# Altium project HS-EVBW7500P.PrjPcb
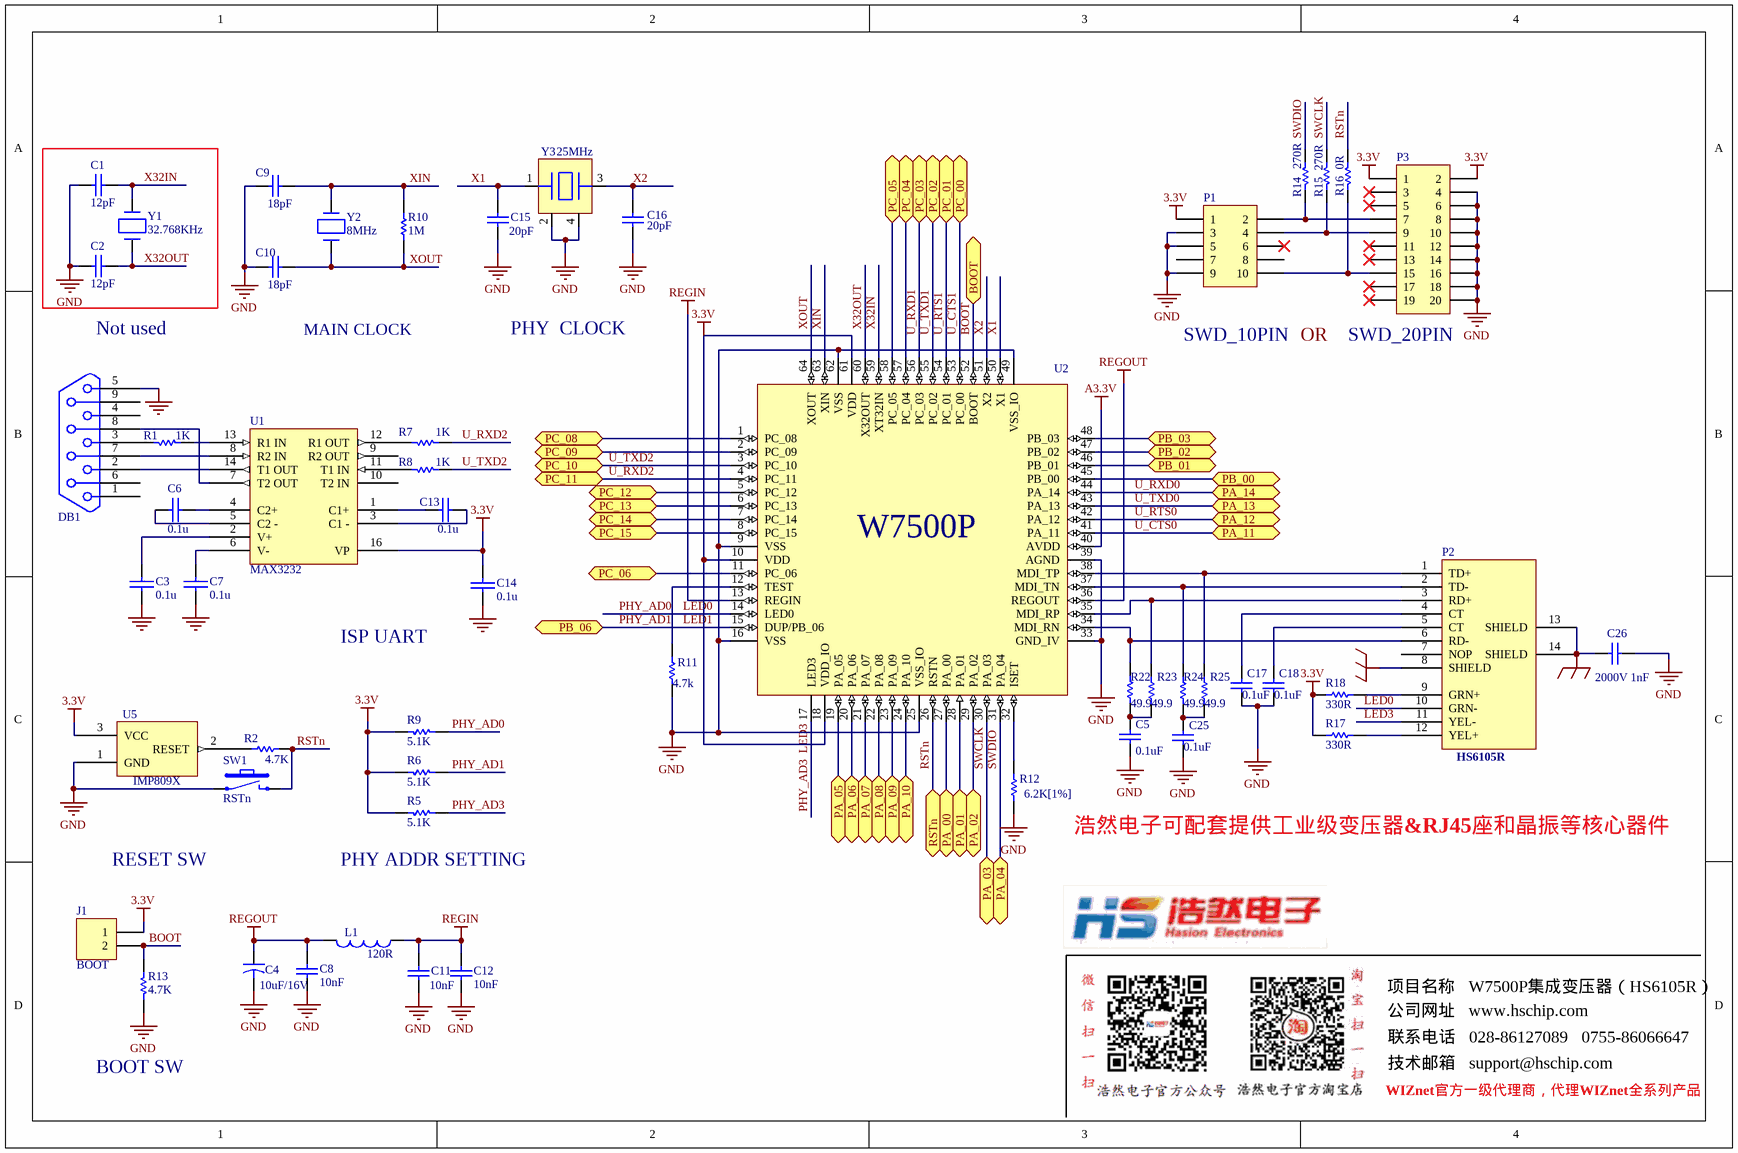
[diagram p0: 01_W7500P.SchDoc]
2 sheets, 77 parts. Net scope: flat (ports and power ports of the same name join across sheets).
Sheets:
  01_W7500P.SchDoc
  02_Power and Arduino.SchDoc

## Sheet 01_W7500P.SchDoc
size 325 x 214 mm; PageSetup: Record=PageOptions?CenterHorizontal=True?CenterVertical=True?PrintScale=1.00?XCorrection=1.00?YCorrection=1.00?PrintKind=0?BorderSize=5000000?LeftOffset=0?BottomOffset=0?Orientation=2?PaperLength=1000?PaperWidth=1000?Scale=100?PaperSource=7?PrintQuality=-3?MediaType=1?DitherType=10?PaperKind=A4?PrintScaleMode=1

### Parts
C1  12pF  [0603]
C2  12pF  [0603]
C3  0.1u  [0603]
C4  10uF/16V  [CAP-A Size]
C5  0.1uF  [0603]
C6  0.1u  [0603]
C7  0.1u  [0603]
C8  10nF  [0603]
C9  18pF  [0603]
C10  18pF  [0603]
C11  10nF  [0603]
C12  10nF  [0603]
C13  0.1u  [0603]
C14  0.1u  [0603]
C15  20pF  [0603]
C16  20pF  [0603]
C17  0.1uF  [0603]
C18  0.1uF  [0603]
C25  0.1uF  [0603]
C26  2000V 1nF  [0603]
DB1  DB9  [DB9RA/F]  (value not drawn)
J1  BOOT  [IDC-1X2]
L1  120R  [0603]
P1  SWD_10PIN  [IDC(SMD)-2X5(1.27MM)]
P2  HS6105R  [RJ45]
P3  SWD_20PIN  [HDR2X10]
R1  1K  [0603]
R2  4.7K  [0603]
R5  5.1K  [0603]
R6  5.1K  [0603]
R7  1K  [0603]
R8  1K  [0603]
R9  5.1K  [0603]
R10  1M  [0603]
R11  4.7k  [0603]
R12  6.2K[1%]  [0603]
R13  4.7K  [0603]
R14  270R  [0603]
R15  270R  [0603]
R16  0R  [0603]
R17  330R  [0603]
R18  330R  [0603]
R22  49.9  [0603]
R23  49.9  [0603]
R24  49.9  [0603]
R25  49.9  [0603]
SW1  RSTn  [直插上位按键]
U1  MAX3232  [SO-16]
U2  W7500P  [LQFP64-W7500P]
U5  IMP809X  [SOT-23]
Y1  32.768KHz  [OSC-CH206-RA]
Y2  8MHz  [XTAL-49S]
Y3  25MHz  [XTAL-49S]

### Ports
BOOT (bidir), PA_00, PA_01, PA_02, PA_03, PA_04, PA_05, PA_06, PA_07, PA_08, PA_09, PA_10, PA_11, PA_12, PA_13, PA_14, PB_00, PB_01, PB_02, PB_03 (bidir), PB_06, PC_00, PC_01, PC_02, PC_03, PC_04, PC_05, PC_06, PC_08, PC_09, PC_10, PC_11, PC_12, PC_13, PC_14, PC_15, RSTn

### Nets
3.3V: C14.1 J1.1 P1.1 P3.1 P3.2 R5.2 R6.2 R9.2 R17.1 R18.2 U1.16(VP) U2.10(VDD) U2.18(VDD_IO) U2.61(VDD) U5.3(VCC)
A3.3V: U2.40(AVDD)
EGND: C26.1 P2.13(SHIELD) P2.14(SHIELD)
EGND1: P2.8(SHIELD)
GND: C1.1 C2.1 C3.2 C4.2 C5.1 C7.2 C8.1 C9.1 C10.1 C11.1 C12.1 C14.2 C15.1 C16.1 C17.1 C18.1 C25.1 C26.2 DB1.5 P1.3 P1.5 P1.9 P3.4 P3.6 P3.8 P3.10 P3.12 P3.14 P3.16 P3.18 P3.20 R11.2 R12.2 R13.1 SW1.1 U1.15(GND) U2.9(VSS) U2.16(VSS) U2.25(VSS_IO) U2.33(GND_IV) U2.39(AGND) U2.49(VSS_IO) U2.62(VSS) U5.1(GND) Y3.2 Y3.4
REGIN: C11.2 C12.2 L1.1 U2.13(REGIN)
REGOUT: C4.1 C8.2 L1.2 U2.36(REGOUT)
BOOT: J1.2 R13.2 U2.52(BOOT) ; port BOOT
INPUT1: U2.5(PC_12) ; port PC_12
INPUT2: U2.6(PC_13) ; port PC_13
LED0: P2.10(GRN-) R9.1 U2.14(LED0)  [also labelled PHY_AD0]
LED1: R6.1 U2.15(DUP/PB_06) ; port PB_06  [also labelled PHY_AD1]
LED3: P2.11(YEL-) R5.1 U2.17(LED3)  [also labelled PHY_AD3]
OUTPUT1: U2.7(PC_14) ; port PC_14
OUTPUT2: U2.8(PC_15) ; port PC_15
RSTn: R2.1 R16.1 SW1.2 U2.26(RSTN) ; port RSTn
SWCLK: R15.1 U2.30(PA_03) ; port PA_03
SWDIO: R14.1 U2.31(PA_04) ; port PA_04
U_CTS0: U2.41(PA_11) ; port PA_11
U_CTS1: U2.53(PC_00) ; port PC_00
U_RTS0: U2.42(PA_12) ; port PA_12
U_RTS1: U2.54(PC_01) ; port PC_01
U_RXD0: U2.44(PA_14) ; port PA_14
U_RXD1: U2.56(PC_03) ; port PC_03
U_RXD2: R7.2 U2.4(PC_11) ; port PC_11
U_TXD0: U2.43(PA_13) ; port PA_13
U_TXD1: U2.55(PC_02) ; port PC_02
U_TXD2: R8.2 U2.3(PC_10) ; port PC_10
X1: C15.2 U2.50(X1) Y3.1
X2: C16.2 U2.51(X2) Y3.3
X32IN: C1.2 U2.59(XT32IN) Y1.2
X32OUT: C2.2 U2.60(X32OUT) Y1.1
XIN: C9.2 R10.1 U2.63(XIN) Y2.1
XOUT: C10.2 R10.2 U2.64(XOUT) Y2.2
NetC3_1: C3.1 U1.2(V+)
NetC5_2: C5.2 R22.2 R23.2
NetC6_1: C6.1 U1.4(C2+)
NetC6_2: C6.2 U1.5(C2_-)
NetC7_1: C7.1 U1.6(V-)
NetC13_1: C13.1 U1.3(C1_-)
NetC13_2: C13.2 U1.1(C1+)
NetC17_2: C17.2 P2.4(CT)
NetC18_2: C18.2 P2.5(CT)
NetC25_2: C25.2 R24.2 R25.2
NetDB1_2: DB1.2 U1.14(T1_OUT)
NetDB1_3: DB1.3 R1.1
NetDB1_7: DB1.7 U1.8(R2_IN)
NetDB1_8: DB1.8 U1.7(T2_OUT)
NetJ3_1: U2.27(PA_00) ; port PA_00
NetJ3_2: U2.28(PA_01) ; port PA_01
NetJ3_3: U2.29(PA_02) ; port PA_02
NetJ3_6: U2.19(PA_05) ; port PA_05
NetJ3_7: U2.20(PA_06) ; port PA_06
NetJ3_8: U2.21(PA_07) ; port PA_07
NetJ3_9: U2.22(PA_08) ; port PA_08
NetJ3_10: U2.23(PA_09) ; port PA_09
NetJ3_11: U2.24(PA_10) ; port PA_10
NetJ3_17: U2.45(PB_00) ; port PB_00
NetJ3_18: U2.46(PB_01) ; port PB_01
NetJ3_19: U2.47(PB_02) ; port PB_02
NetJ3_20: U2.48(PB_03) ; port PB_03
NetJ4_5: U2.57(PC_04) ; port PC_04
NetJ4_6: U2.58(PC_05) ; port PC_05
NetJ4_7: U2.11(PC_06) ; port PC_06
NetJ4_9: U2.1(PC_08) ; port PC_08
NetJ4_10: U2.2(PC_09) ; port PC_09
NetP1_2: P1.2 P3.7 R14.2
NetP1_4: P1.4 P3.9 R15.2
NetP1_10: P1.10 P3.15 R16.2
NetP2_1: P2.1(TD+) R25.1 U2.38(MDI_TP)
NetP2_2: P2.2(TD-) R24.1 U2.37(MDI_TN)
NetP2_3: P2.3(RD+) R23.1 U2.35(MDI_RP)
NetP2_6: P2.6(RD-) R22.1 U2.34(MDI_RN)
NetP2_9: P2.9(GRN+) R18.1
NetP2_12: P2.12(YEL+) R17.2
NetR1_2: R1.2 U1.13(R1_IN)
NetR2_2: R2.2 U5.2(RESET)
NetR7_1: R7.1 U1.12(R1_OUT)
NetR8_1: R8.1 U1.11(T1_IN)
NetR11_1: R11.1 U2.12(TEST)
NetR12_1: R12.1 U2.32(ISET)

Not connected (* = marked no-connect by the designer): DB1 1 4 6 9; P1 6* 7 8; P2 7(NOP); P3 3* 5* 11* 13* 17* 19*; U1 9(R2_OUT) 10(T2_IN)

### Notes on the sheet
- Not used
- MAIN CLOCK
- PHY  CLOCK
- OR
- ISP UART
- RESET SW
- (near R5) PHY ADDR SETTING
- 公司网址   www.hschip.com
- 项目名称   W7500P集成变压器（HS6105R）
- BOOT SW
- WIZnet官方一级代理商，代理WIZnet全系列产品
- 联系电话   028-86127089   0755-86066647
- 技术邮箱   support@hschip.com
- Labels drawn without touching a wire or pin: 浩然电子可配套提供工业级变压器&RJ45座和晶振等核心器件

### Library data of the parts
C1 C2 C5 C8-C12 C15-C18 C25 C26 = CAP-0603: Ceramic CAP 0603(1608)
C3 C6 C7 C13 C14 = CAP: Capacitor
C4 = CAP-A Size: Tantla CAP A Size EIA/IECQ 3216
DB1 = ICHIP3.S01_DB9_1
J1 = Header 2: Header, 2-Pin
L1 = IND-0603: Inductor 0603(1608)
P1 = Header 5X2: Header, 5-Pin, Dual row
P2 = LU1T516_1: LU1T516
P3 = Header 10X2: Header, 10-Pin, Dual row
R1 R2 R5-R18 R22-R25 = RES-0603
SW1 = IT-1101NHA-180G: TACT Switch (SMD)
U1 = MAX232ACPE(16): +-15KV ESD-PROTECTED, +5V RS-232 TRANSCEIVERS
U2 = W7500P: WIZnet ARM Cortex-M0
Y1 = CH-206-32.768KHz/12.5pF
Y2 = ATS Type: ATS Type Crystal
Y3 = 82J0626-25MHz: X-tal 25MHz,3.2x2.5 SMD, CL=18pF

## Sheet 02_Power and Arduino.SchDoc
size 292 x 193 mm; PageSetup: Record=PageOptions?CenterHorizontal=True?CenterVertical=True?PrintScale=1.00?XCorrection=1.00?YCorrection=1.00?PrintKind=0?BorderSize=5000000?LeftOffset=0?BottomOffset=0?Orientation=2?PaperLength=1000?PaperWidth=1000?Scale=100?PaperSource=7?PrintQuality=-3?MediaType=1?DitherType=10?PaperKind=A4?PrintScaleMode=1
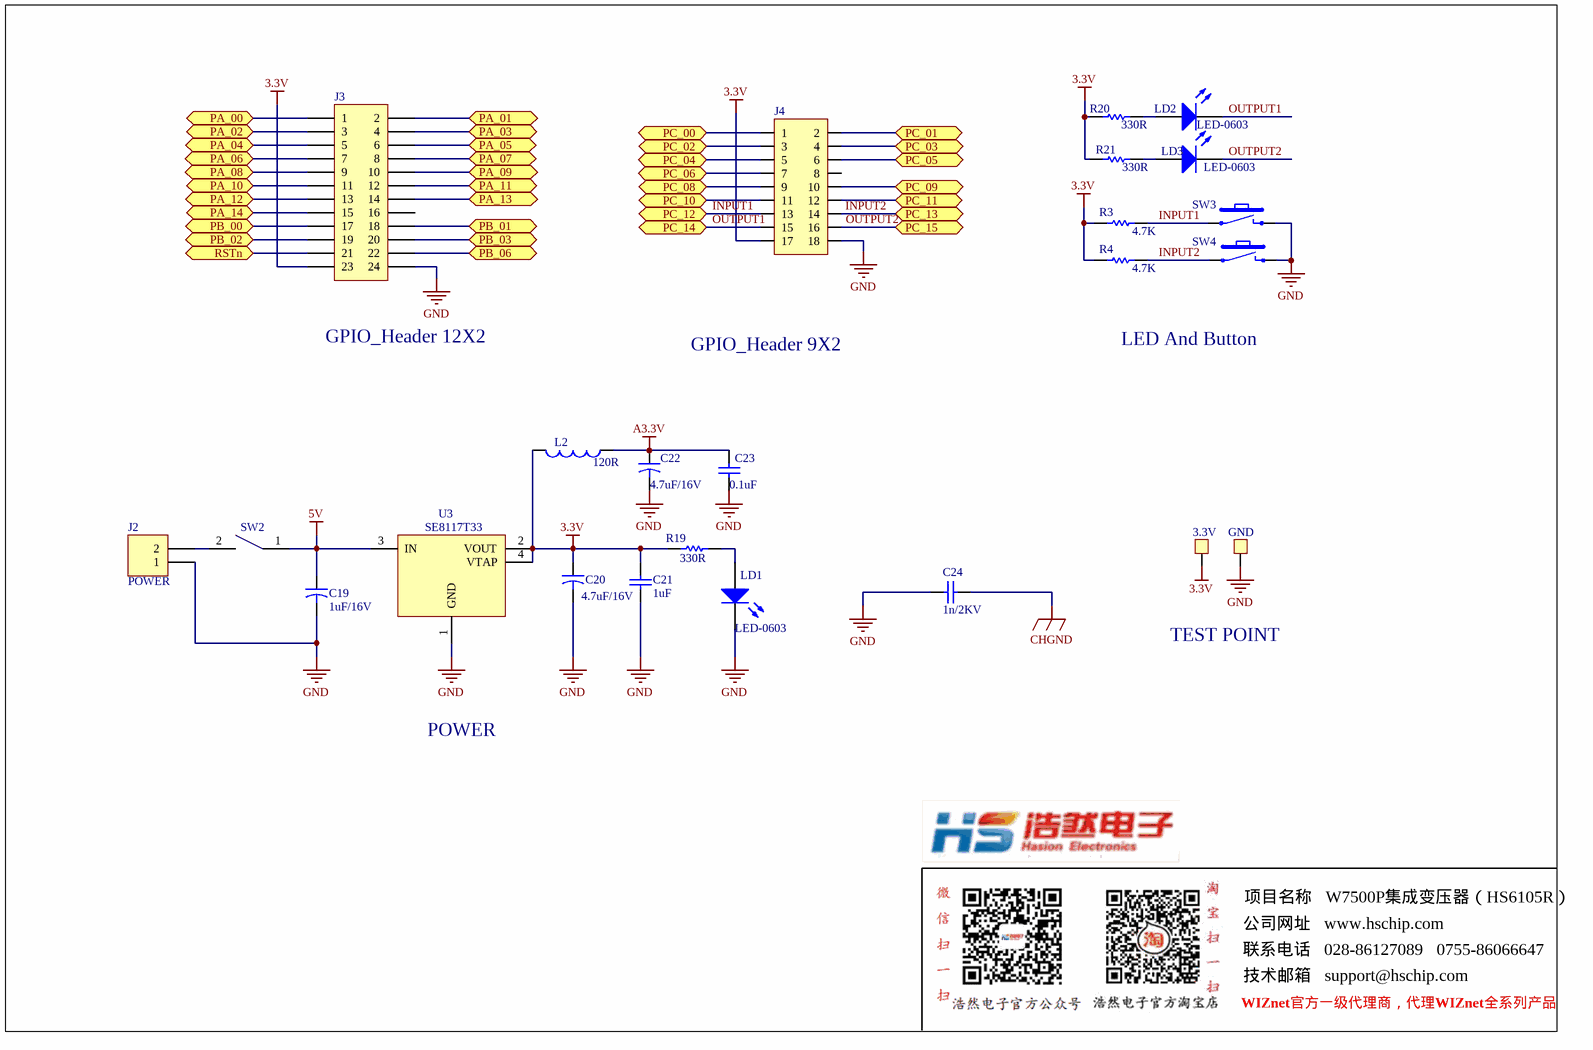
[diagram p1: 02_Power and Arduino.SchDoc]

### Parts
3.3V  3.3V  [TEST POINT]  (value not drawn)
C19  1uF/16V  [CAP-A Size]
C20  4.7uF/16V  [CAP-A Size]
C21  1uF  [0603]
C22  4.7uF/16V  [CAP-A Size]
C23  0.1uF  [0603]
C24  1n/2KV  [CAP-1808]
GND  GND  [TEST POINT]  (value not drawn)
J2  POWER  [PLUG]
J3  GPIO_Header 12X2  [HDR2X12]
J4  2.54mm 2x9 Pin Header DIP  [IDC-2X9]  (value not drawn)
L2  120R  [0603]
LD1  LED-0603  [LED-0603-RED]
LD2  LED-0603  [LED-0603-RED]
LD3  LED-0603  [LED-0603-RED]
R3  4.7K  [0603]
R4  4.7K  [0603]
R19  330R  [0603]
R20  330R  [0603]
R21  330R  [0603]
SW2  SW  [SWITCH-3]  (value not drawn)
SW3  (no value)  [直插上位按键]
SW4  (no value)  [直插上位按键]
U3  SE8117T33  [SOT-223]

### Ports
PA_00 (bidir), PA_01 (bidir), PA_02 (bidir), PA_03 (bidir), PA_04 (bidir), PA_05 (bidir), PA_06 (bidir), PA_07 (bidir), PA_08 (bidir), PA_09 (bidir), PA_10 (bidir), PA_11 (bidir), PA_12 (bidir), PA_13 (bidir), PA_14 (bidir), PB_00 (bidir), PB_01 (bidir), PB_02 (bidir), PB_03 (bidir), PB_06 (bidir), PC_00 (bidir), PC_01 (bidir), PC_02 (bidir), PC_03 (bidir), PC_04 (bidir), PC_05 (bidir), PC_06 (bidir), PC_08 (bidir), PC_09 (bidir), PC_10, PC_11, PC_12, PC_13, PC_14, PC_15, RSTn (bidir)

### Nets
3.3V: 3.3V.1(TETSPOINT) C20.1 C21.2 J3.23 J4.17 L2.2 R3.2 R4.2 R19.1 R20.1 R21.1 U3.2(VOUT) U3.4(VTAP)
5V: C19.1 SW2.1 U3.3(IN)
A3.3V: C22.1 C23.2 L2.1
CHGND: C24.2
GND: C19.2 C20.2 C21.1 C22.2 C23.1 C24.1 GND.1(TETSPOINT) J2.1 J3.24 J4.18 LD1.2(K) SW3.2 SW4.2 U3.1(GND)
INPUT1: J4.13 R3.1 SW3.1 ; port PC_12
INPUT2: J4.14 R4.1 SW4.1 ; port PC_13
LED1: J3.22 ; port PB_06
OUTPUT1: J4.15 LD2.2(K) ; port PC_14
OUTPUT2: J4.16 LD3.2(K) ; port PC_15
RSTn: J3.21 ; port RSTn
SWCLK: J3.4 ; port PA_03
SWDIO: J3.5 ; port PA_04
U_CTS0: J3.12 ; port PA_11
U_CTS1: J4.1 ; port PC_00
U_RTS0: J3.13 ; port PA_12
U_RTS1: J4.2 ; port PC_01
U_RXD0: J3.15 ; port PA_14
U_RXD1: J4.4 ; port PC_03
U_RXD2: J4.12 ; port PC_11
U_TXD0: J3.14 ; port PA_13
U_TXD1: J4.3 ; port PC_02
U_TXD2: J4.11 ; port PC_10
NetJ2_2: J2.2 SW2.2
NetJ3_1: J3.1 ; port PA_00
NetJ3_2: J3.2 ; port PA_01
NetJ3_3: J3.3 ; port PA_02
NetJ3_6: J3.6 ; port PA_05
NetJ3_7: J3.7 ; port PA_06
NetJ3_8: J3.8 ; port PA_07
NetJ3_9: J3.9 ; port PA_08
NetJ3_10: J3.10 ; port PA_09
NetJ3_11: J3.11 ; port PA_10
NetJ3_17: J3.17 ; port PB_00
NetJ3_18: J3.18 ; port PB_01
NetJ3_19: J3.19 ; port PB_02
NetJ3_20: J3.20 ; port PB_03
NetJ4_5: J4.5 ; port PC_04
NetJ4_6: J4.6 ; port PC_05
NetJ4_7: J4.7 ; port PC_06
NetJ4_9: J4.9 ; port PC_08
NetJ4_10: J4.10 ; port PC_09
NetLD1_1: LD1.1(A) R19.2
NetLD2_1: LD2.1(A) R20.2
NetLD3_1: LD3.1(A) R21.2

Not connected (* = marked no-connect by the designer): J3 16; J4 8

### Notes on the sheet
- GPIO_Header 9X2
- LED And Button
- TEST POINT
- POWER
- 项目名称   W7500P集成变压器（HS6105R）
- 公司网址   www.hschip.com
- 联系电话   028-86127089   0755-86066647
- 技术邮箱   support@hschip.com
- WIZnet官方一级代理商，代理WIZnet全系列产品

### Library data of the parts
3.3V GND = TESTPOINT: TEST POINT
C19 C20 C22 = CAP-A Size: Tantla CAP A Size EIA/IECQ 3216
C21 C23 = CAP-0603: Ceramic CAP 0603(1608)
C24 = CAP-1808: Ceramic CAP 1808(4520)
J2 = Header 2: Header, 2-Pin
J3 = Header 12X2: Header, 12-Pin, Dual row
L2 = IND-0603: Inductor 0603(1608)
R3 R4 R19-R21 = RES-0603
SW2 = swtch
SW3 SW4 = IT-1101NHA-180G: TACT Switch (SMD)
U3 = AME8815BEGT330Z: 1.5A CMOS LDO

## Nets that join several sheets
3.3V: 01_W7500P (15 pins), 02_Power and Arduino (13 pins)
A3.3V: 01_W7500P (U2.40), 02_Power and Arduino (C22.1 C23.2 L2.1)
GND: 01_W7500P (46 pins), 02_Power and Arduino (14 pins)
INPUT1: 01_W7500P (U2.5), 02_Power and Arduino (J4.13 R3.1 SW3.1)
INPUT2: 01_W7500P (U2.6), 02_Power and Arduino (J4.14 R4.1 SW4.1)
LED1: 01_W7500P (R6.1 U2.15), 02_Power and Arduino (J3.22)
NetJ3_1: 01_W7500P (U2.27), 02_Power and Arduino (J3.1)
NetJ3_2: 01_W7500P (U2.28), 02_Power and Arduino (J3.2)
NetJ3_3: 01_W7500P (U2.29), 02_Power and Arduino (J3.3)
NetJ3_6: 01_W7500P (U2.19), 02_Power and Arduino (J3.6)
NetJ3_7: 01_W7500P (U2.20), 02_Power and Arduino (J3.7)
NetJ3_8: 01_W7500P (U2.21), 02_Power and Arduino (J3.8)
NetJ3_9: 01_W7500P (U2.22), 02_Power and Arduino (J3.9)
NetJ3_10: 01_W7500P (U2.23), 02_Power and Arduino (J3.10)
NetJ3_11: 01_W7500P (U2.24), 02_Power and Arduino (J3.11)
NetJ3_17: 01_W7500P (U2.45), 02_Power and Arduino (J3.17)
NetJ3_18: 01_W7500P (U2.46), 02_Power and Arduino (J3.18)
NetJ3_19: 01_W7500P (U2.47), 02_Power and Arduino (J3.19)
NetJ3_20: 01_W7500P (U2.48), 02_Power and Arduino (J3.20)
NetJ4_5: 01_W7500P (U2.57), 02_Power and Arduino (J4.5)
NetJ4_6: 01_W7500P (U2.58), 02_Power and Arduino (J4.6)
NetJ4_7: 01_W7500P (U2.11), 02_Power and Arduino (J4.7)
NetJ4_9: 01_W7500P (U2.1), 02_Power and Arduino (J4.9)
NetJ4_10: 01_W7500P (U2.2), 02_Power and Arduino (J4.10)
OUTPUT1: 01_W7500P (U2.7), 02_Power and Arduino (J4.15 LD2.2)
OUTPUT2: 01_W7500P (U2.8), 02_Power and Arduino (J4.16 LD3.2)
RSTn: 01_W7500P (R2.1 R16.1 SW1.2 U2.26), 02_Power and Arduino (J3.21)
SWCLK: 01_W7500P (R15.1 U2.30), 02_Power and Arduino (J3.4)
SWDIO: 01_W7500P (R14.1 U2.31), 02_Power and Arduino (J3.5)
U_CTS0: 01_W7500P (U2.41), 02_Power and Arduino (J3.12)
U_CTS1: 01_W7500P (U2.53), 02_Power and Arduino (J4.1)
U_RTS0: 01_W7500P (U2.42), 02_Power and Arduino (J3.13)
U_RTS1: 01_W7500P (U2.54), 02_Power and Arduino (J4.2)
U_RXD0: 01_W7500P (U2.44), 02_Power and Arduino (J3.15)
U_RXD1: 01_W7500P (U2.56), 02_Power and Arduino (J4.4)
U_RXD2: 01_W7500P (R7.2 U2.4), 02_Power and Arduino (J4.12)
U_TXD0: 01_W7500P (U2.43), 02_Power and Arduino (J3.14)
U_TXD1: 01_W7500P (U2.55), 02_Power and Arduino (J4.3)
U_TXD2: 01_W7500P (R8.2 U2.3), 02_Power and Arduino (J4.11)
